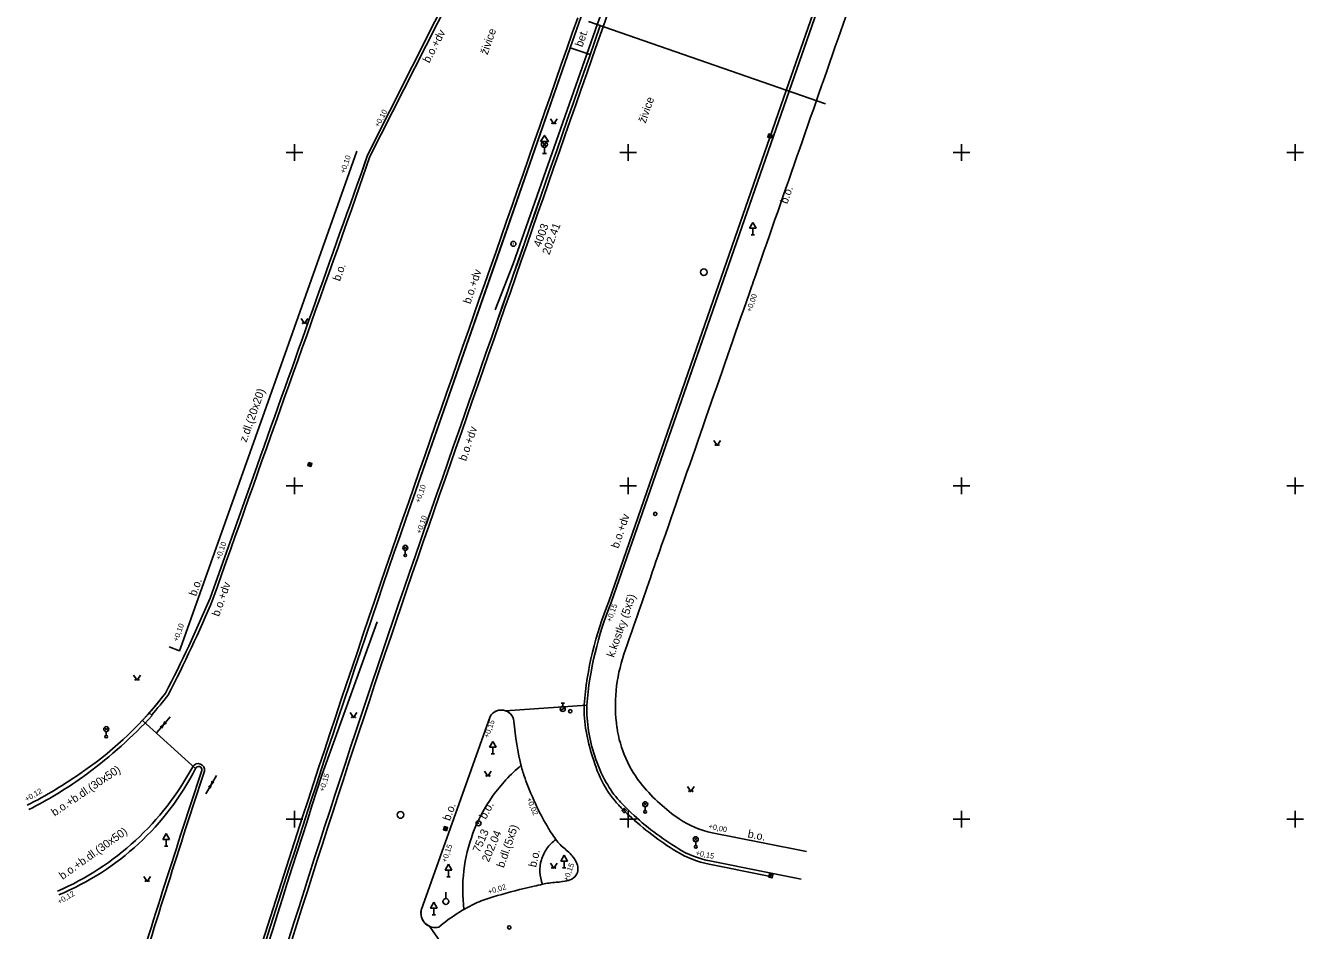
# Model space of a CAD drawing. Extents: x -599151 to -598424, y -1163476 to -1161924.
# Drawn here: x -598645.2 to -598549.4, y -1162208.3 to -1162140.5 of the extents above; entities that cross this region are included whole.
import ezdxf

# ---------------------------------------------------------------- set-up
doc = ezdxf.new("R2010")
doc.units = 0
for name, color, linetype in [('Vrstva 14', 7, 'Continuous'), ('Vrstva 19', 7, 'Continuous'), ('Vrstva 2', 7, 'Continuous'), ('Vrstva 21', 7, 'Continuous'), ('Vrstva 24', 7, 'Continuous'), ('Vrstva 25', 7, 'Continuous'), ('Vrstva 29', 7, 'Continuous'), ('Vrstva 44', 7, 'Continuous'), ('Vrstva 49', 7, 'Continuous'), ('Vrstva 50', 7, 'Continuous'), ('Vrstva 62', 7, 'Continuous'), ('Vrstva 63', 7, 'Continuous'), ('Vrstva 7', 7, 'Continuous')]:
    doc.layers.add(name, color=color, linetype=linetype)

msp = doc.modelspace()

# ---------------------------------------------------------------- linework, layer by layer
at = {"layer": 'Vrstva 14'}
for points in [[(-598605.817, -1162147.455), (-598605.567, -1162147.83), (-598605.317, -1162147.455)], [(-598624.504, -1162162.44), (-598624.254, -1162162.815), (-598624.004, -1162162.44)], [(-598593.58, -1162171.579), (-598593.33, -1162171.954), (-598593.08, -1162171.579)], [(-598637.064, -1162189.181), (-598636.814, -1162189.556), (-598636.564, -1162189.181)], [(-598620.834, -1162191.994), (-598620.584, -1162192.369), (-598620.334, -1162191.994)], [(-598610.755, -1162196.383), (-598610.505, -1162196.758), (-598610.255, -1162196.383)], [(-598595.551, -1162197.538), (-598595.301, -1162197.913), (-598595.051, -1162197.538)], [(-598605.828, -1162203.288), (-598605.578, -1162203.663), (-598605.328, -1162203.288)], [(-598636.299, -1162204.28), (-598636.049, -1162204.655), (-598635.799, -1162204.28)]]:
    msp.add_lwpolyline(points, dxfattribs=at)
for centre in [(-598605.692, -1162147.805), (-598605.442, -1162147.805), (-598624.379, -1162162.79), (-598624.129, -1162162.79), (-598593.455, -1162171.929), (-598593.205, -1162171.929), (-598636.939, -1162189.531), (-598636.689, -1162189.531), (-598620.709, -1162192.344), (-598620.459, -1162192.344), (-598610.63, -1162196.733), (-598610.38, -1162196.733), (-598595.426, -1162197.888), (-598595.176, -1162197.888), (-598605.703, -1162203.638), (-598605.453, -1162203.638), (-598636.174, -1162204.63), (-598635.924, -1162204.63)]:
    msp.add_circle(centre, 0.025, dxfattribs=at)
at = {"layer": 'Vrstva 19'}
for p, q in [((-598590.66, -1162155.238), (-598590.91, -1162155.671)), ((-598590.91, -1162155.671), (-598590.41, -1162155.671)), ((-598590.66, -1162155.238), (-598590.41, -1162155.671)), ((-598590.66, -1162156.171), (-598590.66, -1162155.671)), ((-598590.785, -1162156.171), (-598590.535, -1162156.171)), ((-598610.14, -1162194.157), (-598610.39, -1162194.59)), ((-598610.14, -1162194.157), (-598609.89, -1162194.59)), ((-598610.39, -1162194.59), (-598609.89, -1162194.59)), ((-598610.265, -1162195.09), (-598610.015, -1162195.09)), ((-598610.14, -1162195.09), (-598610.14, -1162194.59)), ((-598634.63, -1162201.067), (-598634.88, -1162201.5)), ((-598634.88, -1162201.5), (-598634.38, -1162201.5)), ((-598634.63, -1162201.067), (-598634.38, -1162201.5)), ((-598634.63, -1162202), (-598634.63, -1162201.5)), ((-598634.755, -1162202), (-598634.505, -1162202)), ((-598604.79, -1162202.698), (-598605.04, -1162203.131)), ((-598604.79, -1162202.698), (-598604.54, -1162203.131)), ((-598613.47, -1162203.367), (-598613.72, -1162203.8)), ((-598613.72, -1162203.8), (-598613.22, -1162203.8)), ((-598613.47, -1162203.367), (-598613.22, -1162203.8)), ((-598613.47, -1162204.3), (-598613.47, -1162203.8)), ((-598605.04, -1162203.131), (-598604.54, -1162203.131)), ((-598604.915, -1162203.631), (-598604.665, -1162203.631)), ((-598604.79, -1162203.631), (-598604.79, -1162203.131)), ((-598613.595, -1162204.3), (-598613.345, -1162204.3)), ((-598614.56, -1162206.218), (-598614.81, -1162206.651)), ((-598614.81, -1162206.651), (-598614.31, -1162206.651)), ((-598614.56, -1162206.218), (-598614.31, -1162206.651)), ((-598614.56, -1162207.151), (-598614.56, -1162206.651)), ((-598614.685, -1162207.151), (-598614.435, -1162207.151))]:
    msp.add_line(p, q, dxfattribs=at)
at = {"layer": 'Vrstva 2'}
for centre, radius in [((-598608.6, -1162156.84), 0.187), ((-598608.6, -1162156.84), 0.00896), ((-598611.21, -1162200.3), 0.187), ((-598611.21, -1162200.3), 0.00896)]:
    msp.add_circle(centre, radius, dxfattribs=at)
at = {"layer": 'Vrstva 21'}
for points in [[(-598609.96, -1162161.79), (-598608.61, -1162158.34), (-598602.3, -1162140.35), (-598596.47, -1162124.26), (-598595.28, -1162120.14)], [(-598618.82, -1162185.2), (-598622.95, -1162196.68)]]:
    msp.add_lwpolyline(points, dxfattribs=at)
msp.add_arc((-597493.021, -1162563.384), 1187.944, 162.019831, 163.896006, dxfattribs=at)
at = {"layer": 'Vrstva 24'}
for p, q in [((-598605.025, -1162191.282), (-598604.775, -1162191.282)), ((-598604.9, -1162191.532), (-598604.9, -1162191.282)), ((-598605.047, -1162191.836), (-598604.752, -1162191.604))]:
    msp.add_line(p, q, dxfattribs=at)
for centre, radius in [((-598597.96, -1162177.09), 0.125), ((-598604.9, -1162191.72), 0.188), ((-598604.34, -1162191.89), 0.125), ((-598608.91, -1162208.111), 0.125)]:
    msp.add_circle(centre, radius, dxfattribs=at)
at = {"layer": 'Vrstva 25'}
for p, q in [((-598589.413, -1162148.878), (-598589.327, -1162148.642)), ((-598623.819, -1162173.272), (-598623.901, -1162173.508)), ((-598600.205, -1162199.432), (-598600.375, -1162199.248)), ((-598613.726, -1162200.82), (-598613.654, -1162200.58)), ((-598589.433, -1162204.219), (-598589.187, -1162204.267))]:
    msp.add_line(p, q, dxfattribs=at)
for points in [[(-598589.295, -1162148.92), (-598589.21, -1162148.685), (-598589.445, -1162148.6), (-598589.53, -1162148.835)], [(-598623.936, -1162173.231), (-598624.019, -1162173.466), (-598623.784, -1162173.549), (-598623.701, -1162173.314)], [(-598600.113, -1162199.347), (-598600.283, -1162199.163), (-598600.467, -1162199.333), (-598600.297, -1162199.517)], [(-598613.606, -1162200.856), (-598613.534, -1162200.616), (-598613.774, -1162200.544), (-598613.846, -1162200.784)], [(-598589.457, -1162204.341), (-598589.212, -1162204.39), (-598589.163, -1162204.145), (-598589.408, -1162204.096)]]:
    msp.add_lwpolyline(points, close=True, dxfattribs=at)
for centre in [(-598594.33, -1162158.97), (-598617.06, -1162199.67)]:
    msp.add_circle(centre, 0.25, dxfattribs=at)
at = {"layer": 'Vrstva 29'}
for p, q in [((-598616.832, -1162179.769), (-598616.568, -1162179.505)), ((-598616.564, -1162179.768), (-598616.828, -1162179.503)), ((-598616.7, -1162180.1), (-598616.7, -1162179.825)), ((-598639.252, -1162193.369), (-598638.988, -1162193.105)), ((-598638.984, -1162193.368), (-598639.248, -1162193.103)), ((-598639.12, -1162193.7), (-598639.12, -1162193.425)), ((-598598.852, -1162199), (-598598.588, -1162198.736)), ((-598598.584, -1162198.999), (-598598.848, -1162198.734)), ((-598598.72, -1162199.331), (-598598.72, -1162199.056)), ((-598595.062, -1162201.629), (-598594.798, -1162201.365)), ((-598594.794, -1162201.628), (-598595.058, -1162201.363)), ((-598594.93, -1162201.96), (-598594.93, -1162201.685))]:
    msp.add_line(p, q, dxfattribs=at)
for centre, radius in [((-598616.7, -1162179.637), 0.188), ((-598616.7, -1162180.2), 0.1), ((-598639.12, -1162193.238), 0.188), ((-598639.12, -1162193.8), 0.1), ((-598598.72, -1162198.869), 0.188), ((-598598.72, -1162199.431), 0.1), ((-598594.93, -1162201.498), 0.188), ((-598594.93, -1162202.06), 0.1)]:
    msp.add_circle(centre, radius, dxfattribs=at)
at = {"layer": 'Vrstva 44'}
for p, q in [((-598602.961, -1162140.169), (-598585.207, -1162146.35)), ((-598606.12, -1162149.22), (-598606.42, -1162149.564)), ((-598606.42, -1162149.22), (-598606.12, -1162149.564)), ((-598606.42, -1162150.07), (-598606.12, -1162150.07)), ((-598606.27, -1162150.07), (-598606.27, -1162149.62)), ((-598613.66, -1162205.936), (-598613.66, -1162205.465))]:
    msp.add_line(p, q, dxfattribs=at)
msp.add_lwpolyline([(-598606.57, -1162149.164), (-598605.97, -1162149.164), (-598606.27, -1162148.714), (-598606.57, -1162149.164)], dxfattribs=at)
for centre, radius in [((-598606.27, -1162149.392), 0.228), ((-598613.66, -1162206.161), 0.225)]:
    msp.add_circle(centre, radius, dxfattribs=at)
at = {"layer": 'Vrstva 49'}
for p, q in [((-598634.325, -1162192.32), (-598634.839, -1162192.922)), ((-598635.354, -1162193.525), (-598634.839, -1162192.922)), ((-598635.069, -1162193.08), (-598634.839, -1162192.922)), ((-598634.839, -1162192.922), (-598634.959, -1162193.175)), ((-598634.839, -1162192.922), (-598634.72, -1162192.669)), ((-598634.61, -1162192.763), (-598634.839, -1162192.922)), ((-598630.845, -1162196.717), (-598631.244, -1162197.401)), ((-598631.244, -1162197.401), (-598631.172, -1162197.13)), ((-598631.643, -1162198.086), (-598631.244, -1162197.401)), ((-598631.442, -1162197.598), (-598631.244, -1162197.401)), ((-598631.244, -1162197.401), (-598631.317, -1162197.671)), ((-598631.046, -1162197.204), (-598631.244, -1162197.401))]:
    msp.add_line(p, q, dxfattribs=at)
at = {"layer": 'Vrstva 62'}
for p, q in [((-598625.625, -1162150), (-598624.375, -1162150)), ((-598625, -1162150.625), (-598625, -1162149.375)), ((-598600.625, -1162150), (-598599.375, -1162150)), ((-598600, -1162150.625), (-598600, -1162149.375)), ((-598575.625, -1162150), (-598574.375, -1162150)), ((-598575, -1162150.625), (-598575, -1162149.375)), ((-598550.625, -1162150), (-598549.375, -1162150)), ((-598550, -1162150.625), (-598550, -1162149.375)), ((-598625.625, -1162175), (-598624.375, -1162175)), ((-598625, -1162175.625), (-598625, -1162174.375)), ((-598600.625, -1162175), (-598599.375, -1162175)), ((-598600, -1162175.625), (-598600, -1162174.375)), ((-598575.625, -1162175), (-598574.375, -1162175)), ((-598575, -1162175.625), (-598575, -1162174.375)), ((-598550.625, -1162175), (-598549.375, -1162175)), ((-598550, -1162175.625), (-598550, -1162174.375)), ((-598625.625, -1162200), (-598624.375, -1162200)), ((-598625, -1162200.625), (-598625, -1162199.375)), ((-598600.625, -1162200), (-598599.375, -1162200)), ((-598600, -1162200.625), (-598600, -1162199.375)), ((-598575.625, -1162200), (-598574.375, -1162200)), ((-598575, -1162200.625), (-598575, -1162199.375)), ((-598550.625, -1162200), (-598549.375, -1162200)), ((-598550, -1162200.625), (-598550, -1162199.375))]:
    msp.add_line(p, q, dxfattribs=at)
at = {"layer": 'Vrstva 63'}
for points in [[(-598619.53, -1162150.2), (-598612.81, -1162136.81), (-598608.35, -1162127.72), (-598604.78, -1162117.61), (-598598.22, -1162098.74), (-598591.99, -1162080.94)], [(-598616.67, -1162177.49), (-598604.34, -1162142.13), (-598602.88, -1162137.92), (-598596.94, -1162120.97), (-598583.85, -1162083.4)], [(-598601.26, -1162183.73), (-598587.93, -1162145.4), (-598574.93, -1162108.09), (-598568.34, -1162089.02)], [(-598627.81, -1162173.48), (-598631.34, -1162183.42)], [(-598615.5, -1162206.8), (-598610.35, -1162192.3)], [(-598609.19, -1162191.86), (-598603.1, -1162191.43)], [(-598632.42, -1162196.19), (-598636.41, -1162192.58)], [(-598611.49, -1162212.91), (-598614.89, -1162208.02)]]:
    msp.add_lwpolyline(points, dxfattribs=at)
for centre, radius, start, end in [((-618776.524, -1155126.009), 21359.084, 340.7215222, 340.8279167), ((-616944.032, -1155645.835), 19444.643, 340.3846444, 340.45745), ((-597355.605, -1162612.887), 1334.112, 160.952203, 162.755986), ((-597604.979, -1162529.476), 1069.597, 160.811292, 162.967156), ((-598718.021, -1162147.04), 94.006, 332.4431, 337.23229), ((-598577.186, -1162193.553), 26.001, 157.80373, 175.31741), ((-598656.21, -1162174.116), 27.074, 316.99933, 322.67847), ((-598609.51, -1162192.765), 0.96, 70.50728, 151.03723), ((-598632.192, -1162196.284), 0.247, 349.31778, 157.50465), ((-597837.748, -1162459.159), 836.562, 161.688844, 162.916781), ((-598614.46, -1162207.042), 1.068, 166.88364, 246.24647)]:
    msp.add_arc(centre, radius, start, end, dxfattribs=at)
at = {"layer": 'Vrstva 7'}
for p, q in [((-598635.895, -1162192.012), (-598635.67, -1162192.21)), ((-598607.66, -1162197.04), (-598607.68, -1162197.05)), ((-598589.328, -1162204.28), (-598589.279, -1162204.032))]:
    msp.add_line(p, q, dxfattribs=at)
for points in [[(-598601.445, -1162183.654), (-598594.65, -1162164.05), (-598588.14, -1162145.33), (-598581.43, -1162126.06), (-598575.13, -1162108.01), (-598568.57, -1162088.94)], [(-598601.26, -1162183.73), (-598594.44, -1162164.13), (-598587.93, -1162145.4), (-598581.22, -1162126.15), (-598574.93, -1162108.09), (-598568.34, -1162089.02)], [(-598586.874, -1162096.809), (-598586.67, -1162096.88), (-598588.68, -1162102.76), (-598601.88, -1162140.559)], [(-598619.53, -1162150.2), (-598612.81, -1162136.81), (-598608.35, -1162127.72)], [(-598619.351, -1162150.29), (-598612.58, -1162136.91), (-598608.17, -1162127.808)], [(-598604.34, -1162142.13), (-598602.88, -1162137.92)], [(-598616.67, -1162177.49), (-598609.8, -1162157.81), (-598604.34, -1162142.13)], [(-598602.848, -1162142.649), (-598604.34, -1162142.13)], [(-598634.41, -1162187.061), (-598633.63, -1162187.361), (-598633.556, -1162187.154), (-598626.86, -1162168.311), (-598620.33, -1162149.891)], [(-598620.4, -1162153.35), (-598619.351, -1162150.29)], [(-598627.81, -1162173.48), (-598631.34, -1162183.42)], [(-598615.5, -1162206.8), (-598610.35, -1162192.3)], [(-598586.638, -1162202.406), (-598589.899, -1162201.758), (-598593.688, -1162201.006)], [(-598593.919, -1162203.367), (-598589.829, -1162204.18), (-598589.328, -1162204.28)], [(-598593.87, -1162203.121), (-598589.78, -1162203.932), (-598587.03, -1162204.481)]]:
    msp.add_lwpolyline(points, dxfattribs=at)
for centre, radius, start, end in [((-612939.478, -1157143.951), 15200.238, 340.8077361, 340.839826), ((-566759.33, -1173270.455), 33733.643, 160.7339722, 160.8015194), ((-618776.524, -1155126.009), 21359.083, 340.7215222, 340.8279167), ((-518609.632, -1190078.753), 84730.764, 160.74766944, 160.77449167), ((-610188.944, -1158101.371), 12287.836, 340.7611833, 340.8077336), ((-616944.033, -1155645.835), 19444.644, 340.3846444, 340.45745), ((-593523.431, -1163918.469), 5363.736, 160.752204, 160.859261), ((-587458.023, -1166141.802), 11853.54, 160.3375806, 160.4921611), ((-598101.002, -1162338.079), 521.098, 159.9886, 160.01751), ((-839291.148, -1078460.584), 254837.762, 340.82132778, 340.82576286), ((-597393.9, -1162600.633), 1294.133, 160.912214, 162.770464), ((-597355.605, -1162612.887), 1334.112, 160.952203, 162.755986), ((-597604.979, -1162529.476), 1069.597, 160.811264, 162.967156), ((-597520.774, -1162556.751), 1157.871, 160.907064, 162.898422), ((-597302.733, -1162628.494), 1370.416, 160.836471, 160.980156), ((-594783.324, -1163497.831), 4035.592, 160.96863, 161.054869), ((-598718.021, -1162147.04), 94.006, 332.4431, 337.23229), ((-598718.844, -1162146.796), 95.085, 332.5175, 337.30669), ((-598577.186, -1162193.553), 26.201, 157.80372, 175.33343), ((-598577.186, -1162193.553), 26.001, 157.80372, 175.31741), ((-598589.128, -1162191.463), 11.821, 161.05487, 188.04041), ((-598656.21, -1162174.116), 27.074, 304.90026, 322.67847), ((-598656.21, -1162174.116), 27.314, 318.62224, 322.67847), ((-598591.775, -1162191.524), 11.525, 179.4865, 199.20691), ((-598661.816, -1162167.954), 35.665, 306.64404, 317.14775), ((-598609.51, -1162192.765), 0.96, 8.07153, 151.03723), ((-598591.752, -1162191.614), 11.349, 179.0693, 198.75311), ((-598585.97, -1162190.686), 22.673, 184.91977, 193.78999), ((-598592.148, -1162191.89), 8.77, 188.04041, 219.47348), ((-598651.17, -1162186.11), 21.028, 293.50889, 331.7887), ((-598650.491, -1162186.914), 20.313, 292.64627, 332.82739), ((-598632.233, -1162196.307), 0.482, 351.09376, 147.69463), ((-598632.192, -1162196.284), 0.247, 349.3188, 157.50652), ((-598600.267, -1162205.289), 12.131, 129.66107, 144.57962), ((-598595.711, -1162192.655), 12.75, 195.62893, 200.16334), ((-598595.939, -1162193.144), 7.062, 197.62724, 197.93084), ((-598592.189, -1162192.378), 10.874, 195.68765, 207.29264), ((-598596.587, -1162193.366), 6.209, 197.7482, 197.78026), ((-598592.511, -1162192.069), 10.487, 197.73267, 209.53668), ((-598660.215, -1162169.119), 33.46, 296.9327, 305.21229), ((-598659.573, -1162170.394), 32.377, 296.92279, 305.20237), ((-598646.678, -1162187.688), 10.489, 303.28596, 304.61623), ((-598652.221, -1162181.142), 19.357, 305.75908, 307.15388), ((-597837.748, -1162459.159), 836.562, 161.688844, 162.916778), ((-597837.204, -1162457.354), 836.314, 161.81715, 163.045864), ((-598586.689, -1162189.43), 22.331, 199.95292, 205.55917), ((-598594.326, -1162193.099), 8.651, 209.53583, 222.50881), ((-598595.073, -1162193.627), 7.49, 208.8293, 221.80228), ((-598588.866, -1162189.187), 13.022, 219.47348, 235.90733), ((-598600.267, -1162205.289), 12.131, 144.57962, 159.49817), ((-598592.368, -1162192.326), 15.959, 204.97391, 211.60833), ((-598595.681, -1162194.341), 6.813, 222.50881, 225.50059), ((-598595.46, -1162194.12), 6.874, 220.88285, 225.46683), ((-598579.839, -1162178.285), 29.116, 225.40789, 226.82874), ((-598579.888, -1162178.27), 29.345, 225.50059, 226.92144), ((-598584.909, -1162183.639), 21.994, 226.92144, 238.5665), ((-598584.844, -1162183.543), 21.858, 226.96843, 238.55124), ((-598592.369, -1162194.362), 6.773, 235.90733, 258.76823), ((-598597.707, -1162195.611), 9.691, 211.60833, 213.85101), ((-598600.267, -1162205.289), 12.131, 159.49817, 173.20867), ((-598603.762, -1162203.838), 2.851, 125.29957, 144.53323), ((-598585.062, -1162187.13), 24.917, 213.85101, 215.24958), ((-598602.665, -1162199.571), 3.361, 215.24958, 232.10756), ((-598603.762, -1162203.838), 2.851, 144.53323, 163.7669), ((-598606.896, -1162205.006), 3.527, 35.6549, 52.10756), ((-598592.449, -1162195.976), 7.535, 238.5665, 258.75452), ((-598592.445, -1162195.976), 7.285, 238.53767, 258.72569), ((-598600.267, -1162205.289), 12.131, 173.20867, 186.91916), ((-598603.762, -1162203.838), 2.851, 163.7669, 182.50314), ((-598605.297, -1162203.86), 1.56, 16.11342, 35.6549), ((-598604.577, -1162203.733), 0.816, 315.79572, 351.69525), ((-598604.764, -1162203.705), 1.004, 351.69525, 16.11342), ((-598603.762, -1162203.838), 2.851, 182.50314, 201.23938), ((-598604.967, -1162211.278), 6.57, 93.75358, 102.77), ((-598605.745, -1162199.422), 5.311, 273.75358, 283.78426), ((-598604.723, -1162203.591), 1.019, 283.78426, 315.79572), ((-598595.402, -1162255.979), 52.278, 103.3348, 106.35731), ((-598590.97, -1162274.677), 71.494, 102.99462, 103.3348), ((-598570.174, -1162364.795), 163.98, 102.77, 102.99462), ((-598605.903, -1162217.929), 12.875, 114.8837, 130.05972), ((-598607.061, -1162216.257), 10.881, 106.35731, 112.9854), ((-598609.758, -1162209.898), 3.973, 112.9854, 112.98555), ((-598614.46, -1162207.042), 1.068, 166.88364, 284.71027)]:
    msp.add_arc(centre, radius, start, end, dxfattribs=at)

# ---------------------------------------------------------------- texts
at = {"layer": 'Vrstva 2'}
for s, rotation, p in [('4003', 69.49315, (-598606.565, -1162157.134)), ('202.41', 69.63879, (-598605.903, -1162157.71)), ('7513', 66.65867, (-598611.131, -1162202.538)), ('202.04', 66.80431, (-598610.448, -1162203.252))]:
    msp.add_text(s, height=0.6, rotation=rotation, dxfattribs=at).set_placement(p)
at = {"layer": 'Vrstva 49'}
for s, height, rotation, p in [('b.o.+dv', 0.6, 62.23979, (-598614.905, -1162143.324)), ('živice', 0.6, 70.83404, (-598610.538, -1162142.704)), ('bet.', 0.6, 70.8078, (-598603.431, -1162142.123)), ('živice', 0.6, 70.83404, (-598598.692, -1162147.836)), ('b.o.', 0.6, 70.82195, (-598588.065, -1162153.889)), ('b.o.', 0.6, 70.36395, (-598621.602, -1162159.687)), ('b.o.+dv', 0.6, 71.46297, (-598611.822, -1162161.388)), ('z.dl.(20x20)', 0.6, 70.44246, (-598628.614, -1162171.768)), ('b.o.+dv', 0.6, 71.46297, (-598612.143, -1162173.174)), ('b.o.+dv', 0.6, 71.46297, (-598600.725, -1162179.726)), ('b.o.', 0.6, 70.36395, (-598632.383, -1162183.312)), ('b.o.+dv', 0.6, 70.63535, (-598630.661, -1162184.833)), ('k.kostky (5x5)', 0.6, 70.64007, (-598601.061, -1162187.898)), ('b.o.+b.dl.(30x50)', 0.59999, 34.13678, (-598642.991, -1162199.794)), ('b.o.', 0.6, 70.44636, (-598613.35, -1162200.16)), ('b.o.', 0.6, 62.31253, (-598610.666, -1162200.049)), ('b.o.+b.dl.(30x50)', 0.6, 35.58664, (-598642.39, -1162204.55)), ('b.dl.(5x5)', 0.6, 70.96863, (-598609.315, -1162203.679)), ('b.o.', 0.6, 348.78439, (-598591.07, -1162201.352)), ('b.o.', 0.6, 77.27, (-598606.896, -1162203.634))]:
    msp.add_text(s, height=height, rotation=rotation, dxfattribs=at).set_placement(p)
at = {"layer": 'Vrstva 50'}
for s, rotation, p in [('+0,10', 62.04489, (-598618.692, -1162148.135)), ('+0,10', 70.8078, (-598621.233, -1162151.602)), ('+0,00', 70.97832, (-598590.781, -1162161.996)), ('+0,10', 70.8078, (-598615.608, -1162176.301)), ('+0,10', 70.8078, (-598615.524, -1162178.621)), ('+0,10', 70.8078, (-598630.562, -1162180.586)), ('+0,15', 70.44636, (-598601.267, -1162185.241)), ('+0,10', 70.43859, (-598633.75, -1162186.71)), ('+0,15', 70.44636, (-598610.46, -1162193.937)), ('+0,15', 72.71765, (-598622.794, -1162197.967)), ('+0,12', 30.48554, (-598645.082, -1162198.693)), ('+0,02', 292.39416, (-598607.62, -1162198.457)), ('+0,00', 348.74646, (-598593.997, -1162200.705)), ('+0,15', 70.44636, (-598613.63, -1162203.274)), ('+0,15', 348.74646, (-598594.962, -1162202.693)), ('+0,15', 70.82195, (-598604.488, -1162204.681)), ('+0,12', 30.48554, (-598642.642, -1162206.392)), ('+0,02', 17.26276, (-598610.434, -1162205.642))]:
    msp.add_text(s, height=0.4, rotation=rotation, dxfattribs=at).set_placement(p)

doc.saveas('drawing.dxf')
